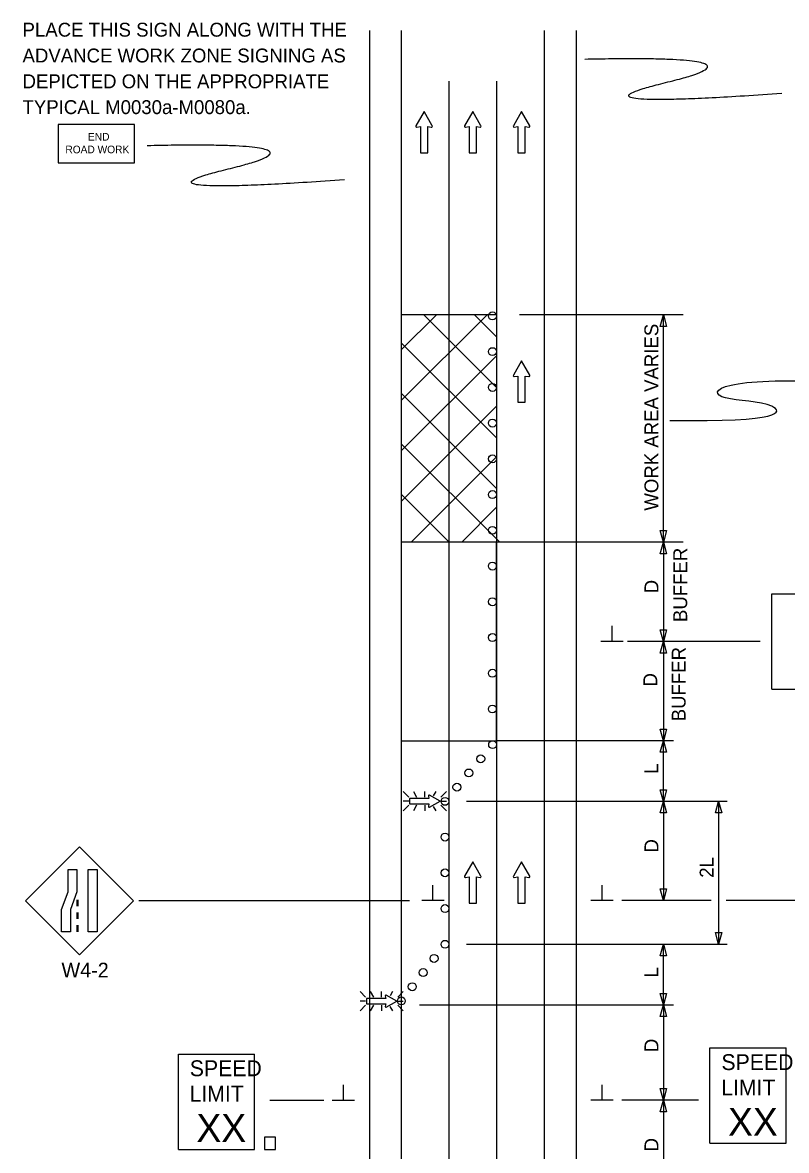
# Model space of a CAD drawing. Extents: x 16726 to 18475, y 5729 to 6921.
# Drawn here: x 16726 to 17111, y 6353 to 6921 of the extents above; entities that cross this region are included whole.
import ezdxf

# ---------------------------------------------------------------- set-up
doc = ezdxf.new("R2010")
doc.units = 0
for name, color, linetype in [('ALI_LEGAL_EX', 7, 'Continuous'), ('MT_SCRATCH_LEVEL_A', 7, 'Continuous'), ('MT_SCRATCH_LEVEL_E', 7, 'Continuous'), ('PAVT_EDGE_EX', 7, 'Continuous'), ('TRAFFIC_SIGNS_PR', 7, 'Continuous'), ('TYPICAL_TEXT_DIMEN_PR', 7, 'Continuous')]:
    doc.layers.add(name, color=color, linetype=linetype)

msp = doc.modelspace()

# ---------------------------------------------------------------- linework, layer by layer
at = {"layer": 'ALI_LEGAL_EX'}
for p, q in [((16941.23, 6891.16), (16941.23, 6061.98)), ((16965.23, 6891.16), (16965.23, 6061.98)), ((16965.23, 6891.16), (16965.23, 6061.98))]:
    msp.add_line(p, q, dxfattribs=at)
for points in [[(16941.23, 6891.16), (16941.23, 6866.16)], [(16965.23, 6891.16), (16965.23, 6866.16)], [(16941.23, 6791.16), (16941.23, 6766.16)], [(16965.23, 6791.16), (16965.23, 6766.16)], [(16941.23, 6691.16), (16941.23, 6666.16)], [(16965.23, 6691.16), (16965.23, 6666.16)], [(16965.23, 6591.16), (16965.23, 6566.16)], [(16941.23, 6491.16), (16941.23, 6466.16)], [(16965.23, 6491.16), (16965.23, 6466.16)], [(16941.23, 6391.16), (16941.23, 6366.16)], [(16965.23, 6391.16), (16965.23, 6366.16)]]:
    msp.add_lwpolyline(points, dxfattribs=at)
at = {"layer": 'MT_SCRATCH_LEVEL_A'}
msp.add_line((16965.23, 6773.54), (16917.23, 6773.54), dxfattribs=at)
at = {"layer": 'MT_SCRATCH_LEVEL_E'}
for p, q in [((16928.67, 6875.95), (16924.56, 6868.71)), ((16928.67, 6875.95), (16924.56, 6868.71)), ((16932.82, 6868.71), (16928.67, 6875.95)), ((16932.82, 6868.71), (16928.67, 6875.95)), ((16953.2, 6875.95), (16949.09, 6868.71)), ((16953.2, 6875.95), (16949.09, 6868.71)), ((16957.35, 6868.71), (16953.2, 6875.95)), ((16957.35, 6868.71), (16953.2, 6875.95)), ((16977.76, 6875.95), (16973.65, 6868.71)), ((16977.76, 6875.95), (16973.65, 6868.71)), ((16981.9, 6868.71), (16977.76, 6875.95)), ((16981.9, 6868.71), (16977.76, 6875.95)), ((16925.04, 6868.03), (16926.82, 6868.34)), ((16925.04, 6868.03), (16926.82, 6868.34)), ((16926.82, 6868.34), (16926.82, 6855.09)), ((16926.82, 6868.34), (16926.82, 6855.09)), ((16930.56, 6855.09), (16930.56, 6868.34)), ((16930.56, 6868.34), (16932.34, 6868.03)), ((16930.56, 6855.09), (16930.56, 6868.34)), ((16930.56, 6868.34), (16932.34, 6868.03)), ((16949.57, 6868.03), (16951.35, 6868.34)), ((16949.57, 6868.03), (16951.35, 6868.34)), ((16951.35, 6868.34), (16951.35, 6855.09)), ((16951.35, 6868.34), (16951.35, 6855.09)), ((16955.09, 6855.09), (16955.09, 6868.34)), ((16955.09, 6868.34), (16956.87, 6868.03)), ((16955.09, 6855.09), (16955.09, 6868.34)), ((16955.09, 6868.34), (16956.87, 6868.03)), ((16974.13, 6868.03), (16975.9, 6868.34)), ((16974.13, 6868.03), (16975.9, 6868.34)), ((16975.9, 6868.34), (16975.9, 6855.09)), ((16975.9, 6868.34), (16975.9, 6855.09)), ((16979.65, 6855.09), (16979.65, 6868.34)), ((16979.65, 6868.34), (16981.42, 6868.03)), ((16979.65, 6855.09), (16979.65, 6868.34)), ((16979.65, 6868.34), (16981.42, 6868.03)), ((16926.82, 6855.09), (16930.56, 6855.09)), ((16926.82, 6855.09), (16930.56, 6855.09)), ((16951.35, 6855.09), (16955.09, 6855.09)), ((16951.35, 6855.09), (16955.09, 6855.09)), ((16975.9, 6855.09), (16979.65, 6855.09)), ((16975.9, 6855.09), (16979.65, 6855.09)), ((16977.76, 6750.29), (16973.65, 6743.05)), ((16977.76, 6750.29), (16973.65, 6743.05)), ((16981.9, 6743.05), (16977.76, 6750.29)), ((16981.9, 6743.05), (16977.76, 6750.29)), ((16974.13, 6742.37), (16975.9, 6742.68)), ((16974.13, 6742.37), (16975.9, 6742.68)), ((16975.9, 6742.68), (16975.9, 6729.43)), ((16975.9, 6742.68), (16975.9, 6729.43)), ((16979.65, 6729.43), (16979.65, 6742.68)), ((16979.65, 6742.68), (16981.42, 6742.37)), ((16979.65, 6729.43), (16979.65, 6742.68)), ((16979.65, 6742.68), (16981.42, 6742.37)), ((16975.9, 6729.43), (16979.65, 6729.43)), ((16975.9, 6729.43), (16979.65, 6729.43)), ((16953.2, 6498.06), (16949.09, 6490.82)), ((16953.2, 6498.06), (16949.09, 6490.82)), ((16957.35, 6490.82), (16953.2, 6498.06)), ((16957.35, 6490.82), (16953.2, 6498.06)), ((16977.76, 6498.06), (16973.65, 6490.82)), ((16977.76, 6498.06), (16973.65, 6490.82)), ((16981.9, 6490.82), (16977.76, 6498.06)), ((16981.9, 6490.82), (16977.76, 6498.06)), ((16949.57, 6490.14), (16951.35, 6490.45)), ((16949.57, 6490.14), (16951.35, 6490.45)), ((16951.35, 6490.45), (16951.35, 6477.2)), ((16951.35, 6490.45), (16951.35, 6477.2)), ((16955.09, 6477.2), (16955.09, 6490.45)), ((16955.09, 6490.45), (16956.87, 6490.14)), ((16955.09, 6477.2), (16955.09, 6490.45)), ((16955.09, 6490.45), (16956.87, 6490.14)), ((16974.13, 6490.14), (16975.9, 6490.45)), ((16974.13, 6490.14), (16975.9, 6490.45)), ((16975.9, 6490.45), (16975.9, 6477.2)), ((16975.9, 6490.45), (16975.9, 6477.2)), ((16979.65, 6477.2), (16979.65, 6490.45)), ((16979.65, 6490.45), (16981.42, 6490.14)), ((16979.65, 6477.2), (16979.65, 6490.45)), ((16979.65, 6490.45), (16981.42, 6490.14)), ((16951.35, 6477.2), (16955.09, 6477.2)), ((16951.35, 6477.2), (16955.09, 6477.2)), ((16975.9, 6477.2), (16979.65, 6477.2)), ((16975.9, 6477.2), (16979.65, 6477.2))]:
    msp.add_line(p, q, dxfattribs=at)
for centre, start, end in [((16924.97, 6868.49), 150.4248, 279.9638), ((16924.97, 6868.49), 150.4248, 279.9638), ((16932.41, 6868.49), 260.0362, 29.7731), ((16932.41, 6868.49), 260.0362, 29.7731), ((16949.49, 6868.49), 150.4248, 279.9638), ((16949.49, 6868.49), 150.4248, 279.9638), ((16956.94, 6868.49), 260.0362, 29.7731), ((16956.94, 6868.49), 260.0362, 29.7731), ((16974.05, 6868.49), 150.4248, 279.9638), ((16974.05, 6868.49), 150.4248, 279.9638), ((16981.49, 6868.49), 260.0362, 29.7731), ((16981.49, 6868.49), 260.0362, 29.7731), ((16974.05, 6742.83), 150.4248, 279.9638), ((16974.05, 6742.83), 150.4248, 279.9638), ((16981.49, 6742.83), 260.0362, 29.7731), ((16981.49, 6742.83), 260.0362, 29.7731), ((16949.49, 6490.6), 150.4248, 279.9638), ((16949.49, 6490.6), 150.4248, 279.9638), ((16956.94, 6490.6), 260.0362, 29.7731), ((16956.94, 6490.6), 260.0362, 29.7731), ((16974.05, 6490.6), 150.4248, 279.9638), ((16974.05, 6490.6), 150.4248, 279.9638), ((16981.49, 6490.6), 260.0362, 29.7731), ((16981.49, 6490.6), 260.0362, 29.7731)]:
    msp.add_arc(centre, 0.463, start, end, dxfattribs=at)
at = {"layer": 'PAVT_EDGE_EX'}
for p, q in [((16901.23, 6916.78), (16901.23, 6061.98)), ((16917.23, 6916.78), (16917.23, 6061.98)), ((16989.23, 6916.78), (16989.23, 6061.98)), ((17005.23, 6916.78), (17005.23, 6061.98)), ((16917.23, 6891.16), (16917.23, 6061.98)), ((16917.23, 6755.83), (16934.94, 6773.54)), ((16917.23, 6730.38), (16960.4, 6773.54)), ((16965.23, 6736.92), (16928.61, 6773.54)), ((16965.23, 6762.38), (16954.06, 6773.54)), ((16965.23, 6711.47), (16917.23, 6759.47)), ((16917.23, 6704.92), (16965.23, 6752.92)), ((16965.23, 6686.01), (16917.23, 6734.01)), ((16917.23, 6679.46), (16965.23, 6727.46)), ((16966.78, 6659.01), (16917.23, 6708.56)), ((16917.23, 6702.97), (16917.23, 6588.44)), ((16922.23, 6659.01), (16965.23, 6702.01)), ((16941.32, 6659.01), (16917.23, 6683.1)), ((16947.69, 6659.01), (16965.23, 6676.55)), ((16917.23, 6588.44), (16917.23, 6559.01)), ((16963.87, 6573.49), (16963.92, 6573.42))]:
    msp.add_line(p, q, dxfattribs=at)
msp.add_lwpolyline([(16965.23, 6659.01), (16917.23, 6659.01), (16917.23, 6559.01), (16965.23, 6559.01)], close=True, dxfattribs=at)
at = {"layer": 'TRAFFIC_SIGNS_PR'}
for p, q in [((17103.87, 6632.9), (17142.27, 6632.9)), ((17103.87, 6584.9), (17103.87, 6632.9)), ((17103.87, 6584.9), (17142.27, 6584.9)), ((16921.01, 6530.55), (16918.18, 6533.37)), ((16923.3, 6533.37), (16924.93, 6530.55)), ((16929.09, 6530.55), (16929.09, 6533.37)), ((16934.56, 6533.37), (16933.35, 6531.27)), ((16939.99, 6533.36), (16937.17, 6530.55)), ((16921.01, 6528.52), (16918.18, 6528.52)), ((16937.17, 6528.52), (16939.99, 6528.52)), ((16921.01, 6526.48), (16918.18, 6523.66)), ((16924.96, 6526.48), (16923.33, 6523.66)), ((16929.09, 6526.48), (16929.09, 6523.66)), ((16933.27, 6525.85), (16934.53, 6523.66)), ((16939.99, 6523.66), (16937.17, 6526.48)), ((16755.14, 6505.46), (16727.99, 6478.31)), ((16782.3, 6478.31), (16755.14, 6505.46)), ((16727.99, 6478.31), (16755.14, 6451.15)), ((16753.9, 6478.8), (16753.9, 6475.6)), ((16754.3, 6478.8), (16754.3, 6475.6)), ((16755.14, 6451.15), (16782.3, 6478.31)), ((16753.9, 6472.4), (16753.9, 6469.2)), ((16754.3, 6472.4), (16754.3, 6469.2)), ((16753.9, 6466), (16753.9, 6462.8)), ((16754.3, 6466), (16754.3, 6462.8)), ((16899.25, 6429.83), (16896.43, 6432.65)), ((16901.55, 6432.65), (16903.17, 6429.83)), ((16907.33, 6429.83), (16907.33, 6432.65)), ((16912.8, 6432.65), (16911.6, 6430.56)), ((16918.24, 6432.65), (16915.42, 6429.83)), ((16899.25, 6427.8), (16896.43, 6427.8)), ((16899.25, 6425.77), (16896.43, 6422.94)), ((16903.2, 6425.77), (16901.57, 6422.94)), ((16907.33, 6425.77), (16907.33, 6422.94)), ((16915.42, 6427.8), (16918.24, 6427.8)), ((16918.24, 6422.95), (16915.42, 6425.77)), ((16911.52, 6425.13), (16912.78, 6422.94)), ((17072.67, 6404.23), (17111.08, 6404.23)), ((17072.67, 6356.23), (17072.67, 6404.23)), ((17111.08, 6356.23), (17111.08, 6404.23)), ((16804.94, 6401.15), (16843.34, 6401.15)), ((16804.94, 6353.15), (16804.94, 6401.15)), ((16843.34, 6353.15), (16843.34, 6401.15)), ((16804.94, 6353.15), (16843.34, 6353.15)), ((17072.67, 6356.23), (17111.08, 6356.23))]:
    msp.add_line(p, q, dxfattribs=at)
for points in [[(16744.44, 6850.13), (16782.84, 6850.13), (16782.84, 6869.33), (16744.44, 6869.33)], [(16753.9, 6494.04), (16753.9, 6482.86), (16750.55, 6473.98), (16750.55, 6462.8), (16746.06, 6462.8), (16746.06, 6473.98), (16749.4, 6482.86), (16749.4, 6494.04)], [(16764.03, 6494.04), (16764.03, 6462.8), (16759.54, 6462.8), (16759.54, 6494.04)], [(16848.35, 6353.15), (16853.95, 6353.15), (16853.95, 6359.32), (16848.35, 6359.32)]]:
    msp.add_lwpolyline(points, close=True, dxfattribs=at)
for points in [[(16930.92, 6531.2), (16931.15, 6529.9), (16921.42, 6529.9), (16921.42, 6527.16), (16931.15, 6527.16), (16930.92, 6525.85)], [(16931.42, 6525.5), (16936.73, 6528.52), (16931.42, 6531.56)], [(16909.16, 6430.48), (16909.39, 6429.18), (16899.67, 6429.18), (16899.67, 6426.44), (16909.39, 6426.44), (16909.16, 6425.14)], [(16909.66, 6424.78), (16914.97, 6427.8), (16909.66, 6430.84)]]:
    msp.add_lwpolyline(points, dxfattribs=at)
for centre in [(16963.13, 6772.96), (16963.13, 6754.96), (16963.13, 6736.96), (16963.13, 6718.96), (16963.13, 6700.96), (16963.13, 6682.96), (16963.13, 6664.96), (16963.13, 6646.96), (16963.13, 6628.96), (16963.13, 6610.96), (16963.13, 6592.96), (16963.13, 6574.96), (16963.23, 6557.01), (16957.23, 6549.87), (16951.23, 6542.73), (16945.23, 6535.59), (16939.23, 6528.44), (16939.23, 6510.44), (16939.23, 6492.44), (16939.23, 6474.44), (16939.23, 6456.44), (16933.73, 6449.31), (16928.24, 6442.19), (16922.74, 6435.06), (16917.24, 6427.93)]:
    msp.add_circle(centre, 2, dxfattribs=at)
for centre, start, end in [((16931.25, 6531.26), 61.4833, 189.9593), ((16931.25, 6525.8), 170.7308, 298.8916), ((16909.5, 6430.54), 61.4833, 189.9593), ((16909.5, 6425.08), 170.7308, 298.8916)]:
    msp.add_arc(centre, 0.341, start, end, dxfattribs=at)
for points in [[(17108.84, 6884.99), (16993.62, 6876.76), (17107.53, 6904.34), (17009.58, 6902.17)], [(16888.57, 6841.49), (16773.34, 6833.26), (16887.25, 6860.84), (16789.31, 6858.67)]]:
    msp.add_open_spline(points, degree=2, dxfattribs=at)
at = {"layer": 'TYPICAL_TEXT_DIMEN_PR'}
for p, q in [((17059.23, 6773.54), (16976.83, 6773.54)), ((17047.66, 6767.68), (17049.23, 6773.54)), ((17049.23, 6659.01), (17049.23, 6773.54)), ((17049.23, 6773.54), (17050.8, 6767.68)), ((17049.23, 6767.68), (17047.66, 6767.68)), ((17050.8, 6767.68), (17049.23, 6767.68)), ((17049.23, 6659.01), (17047.66, 6664.87)), ((17047.66, 6664.87), (17049.23, 6664.87)), ((17049.23, 6664.87), (17050.8, 6664.87)), ((17050.8, 6664.87), (17049.23, 6659.01)), ((17059.23, 6659.01), (16917.23, 6659.01)), ((17047.66, 6653.15), (17049.23, 6659.01)), ((17049.23, 6659.01), (17049.23, 6609.01)), ((17049.23, 6659.01), (17050.8, 6653.15)), ((17049.23, 6653.15), (17047.66, 6653.15)), ((17050.8, 6653.15), (17049.23, 6653.15)), ((17023.35, 6609.01), (17023.35, 6616.79)), ((17049.23, 6609.01), (17047.66, 6614.87)), ((17047.66, 6614.87), (17049.23, 6614.87)), ((17049.23, 6614.87), (17050.8, 6614.87)), ((17050.8, 6614.87), (17049.23, 6609.01)), ((17028.98, 6609.01), (17017.73, 6609.01)), ((17097.91, 6609.01), (17031.11, 6609.01)), ((17047.66, 6603.15), (17049.23, 6609.01)), ((17049.23, 6609.01), (17049.23, 6559.01)), ((17049.23, 6609.01), (17050.8, 6603.15)), ((17049.23, 6603.15), (17047.66, 6603.15)), ((17050.8, 6603.15), (17049.23, 6603.15)), ((17049.23, 6559.01), (17047.66, 6564.87)), ((17047.66, 6564.87), (17049.23, 6564.87)), ((17049.23, 6564.87), (17050.8, 6564.87)), ((17050.8, 6564.87), (17049.23, 6559.01)), ((17054.23, 6559.01), (16965.23, 6559.01)), ((17047.66, 6553.15), (17049.23, 6559.01)), ((17049.23, 6528.44), (17049.23, 6559.01)), ((17049.23, 6559.01), (17050.8, 6553.15)), ((17049.23, 6553.15), (17047.66, 6553.15)), ((17050.8, 6553.15), (17049.23, 6553.15)), ((17049.23, 6528.44), (17047.66, 6534.31)), ((17047.66, 6534.31), (17049.23, 6534.31)), ((17049.23, 6534.31), (17050.8, 6534.31)), ((17050.8, 6534.31), (17049.23, 6528.44)), ((17081.27, 6528.44), (16950.13, 6528.44)), ((17047.66, 6522.58), (17049.23, 6528.44)), ((17049.23, 6528.44), (17049.23, 6478.44)), ((17049.23, 6528.44), (17050.8, 6522.58)), ((17075.47, 6522.58), (17077.04, 6528.44)), ((17077.04, 6528.44), (17078.61, 6522.58)), ((17077.04, 6528.44), (17077.04, 6456.44)), ((17049.23, 6522.58), (17047.66, 6522.58)), ((17050.8, 6522.58), (17049.23, 6522.58)), ((17077.04, 6522.58), (17075.47, 6522.58)), ((17078.61, 6522.58), (17077.04, 6522.58)), ((16933.16, 6478.44), (16933.16, 6486.23)), ((17018.35, 6478.44), (17018.35, 6486.23)), ((17049.23, 6478.44), (17047.66, 6484.31)), ((17047.66, 6484.31), (17049.23, 6484.31)), ((17049.23, 6484.31), (17050.8, 6484.31)), ((17050.8, 6484.31), (17049.23, 6478.44)), ((17077.04, 6483.31), (17077.04, 6479.55)), ((16785.11, 6478.44), (16921.43, 6478.44)), ((16938.78, 6478.44), (16927.53, 6478.44)), ((17023.98, 6478.44), (17012.73, 6478.44)), ((17073.35, 6478.44), (17028.23, 6478.44)), ((17126.81, 6478.44), (17080.85, 6478.44)), ((17077.04, 6456.44), (17075.47, 6462.31)), ((17075.47, 6462.31), (17077.04, 6462.31)), ((17077.04, 6462.31), (17078.61, 6462.31)), ((17078.61, 6462.31), (17077.04, 6456.44)), ((16950.13, 6456.44), (17081.27, 6456.44)), ((17047.66, 6450.58), (17049.23, 6456.44)), ((17049.23, 6425.88), (17049.23, 6456.44)), ((17049.23, 6456.44), (17050.8, 6450.58)), ((17049.23, 6450.58), (17047.66, 6450.58)), ((17050.8, 6450.58), (17049.23, 6450.58)), ((17049.23, 6425.88), (17047.66, 6431.74)), ((17047.66, 6431.74), (17049.23, 6431.74)), ((17049.23, 6431.74), (17050.8, 6431.74)), ((17050.8, 6431.74), (17049.23, 6425.88)), ((16926.39, 6425.88), (17054.23, 6425.88)), ((17047.66, 6420.02), (17049.23, 6425.88)), ((17049.23, 6425.88), (17049.23, 6377.89)), ((17049.23, 6425.88), (17050.8, 6420.02)), ((17049.23, 6420.02), (17047.66, 6420.02)), ((17050.8, 6420.02), (17049.23, 6420.02)), ((16888.1, 6377.89), (16888.1, 6385.67)), ((17018.35, 6377.89), (17018.35, 6385.67)), ((17049.23, 6377.89), (17047.66, 6383.75)), ((17047.66, 6383.75), (17049.23, 6383.75)), ((17049.23, 6383.75), (17050.8, 6383.75)), ((17050.8, 6383.75), (17049.23, 6377.89)), ((16850.93, 6377.89), (16878.23, 6377.89)), ((16882.48, 6377.89), (16893.73, 6377.89)), ((17023.98, 6377.89), (17012.73, 6377.89)), ((17066.87, 6377.89), (17028.23, 6377.89)), ((17047.66, 6372.03), (17049.23, 6377.89)), ((17049.23, 6377.89), (17049.23, 6327.89)), ((17049.23, 6377.89), (17050.8, 6372.03)), ((17049.23, 6372.03), (17047.66, 6372.03)), ((17050.8, 6372.03), (17049.23, 6372.03))]:
    msp.add_line(p, q, dxfattribs=at)
msp.add_open_spline([(17052.38, 6720.3), (17109.65, 6719.38), (17109.65, 6730.13), (17074.74, 6730.13), (17074.74, 6739.18), (17108.94, 6740.94), (17132.27, 6739.83)], degree=3, dxfattribs=at)

# ---------------------------------------------------------------- texts
at = {"layer": 'TRAFFIC_SIGNS_PR'}
for s, height, p in [('PLACE THIS SIGN ALONG WITH THE', 7, (16726.47, 6913.62)), ('ADVANCE WORK ZONE SIGNING AS', 7, (16726.47, 6900.62)), ('DEPICTED ON THE APPROPRIATE', 7, (16726.47, 6887.62)), ('TYPICAL M0030a-M0080a.', 7, (16726.47, 6874.62)), ('END', 3.831, (16759.44, 6861.26)), ('ROAD WORK', 3.831, (16748.05, 6854.88)), ('W4-2', 7.44, (16746.1, 6439.72)), ('SPEED', 8, (16810.7, 6390.01)), ('SPEED', 8, (17078.44, 6393.09)), ('LIMIT', 8, (17078.28, 6380.29)), ('LIMIT', 8, (16810.54, 6377.21)), ('XX', 14.031, (16814.05, 6356.9)), ('XX', 14.031, (17081.79, 6359.99))]:
    msp.add_text(s, height=height, dxfattribs=at).set_placement(p)
at = {"layer": 'TYPICAL_TEXT_DIMEN_PR'}
for s, p in [('WORK AREA VARIES', (17046.67, 6674.86)), ('BUFFER', (17061.2, 6618.76)), ('D', (17046.67, 6633.23)), ('BUFFER', (17060.41, 6568.76)), ('D', (17046.11, 6586.29)), ('L', (17046.67, 6542.3)), ('D', (17046.67, 6502.66)), ('2L', (17074.48, 6489.95)), ('L', (17046.67, 6439.74)), ('D', (17046.67, 6402.11)), ('D', (17046.67, 6352.11))]:
    msp.add_text(s, height=7, rotation=90, dxfattribs=at).set_placement(p)

doc.saveas('drawing.dxf')
